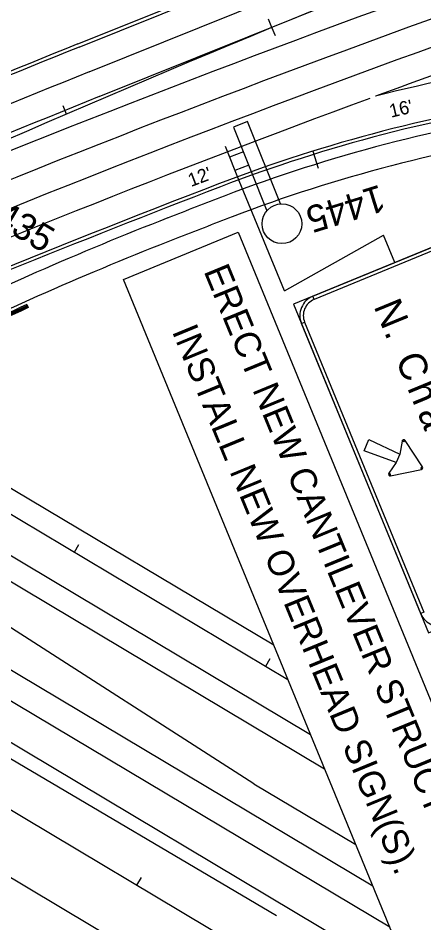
# Model space of a CAD drawing. Extents: x 2338610 to 2351914, y 366540 to 376484.
# Drawn here: x 2349654 to 2349836.1, y 367824.6 to 368230.7 of the extents above; entities that cross this region are included whole.
import ezdxf

# ---------------------------------------------------------------- set-up
doc = ezdxf.new("R2010")
doc.units = 0
for name, color, linetype in [('RD_HC_Cl', 7, 'Continuous'), ('RD_HC_CL_Rel', 7, 'Continuous'), ('RD_PD_Final_LnLine', 7, 'Continuous'), ('RD_PD_Final_TrvlWay', 7, 'Continuous'), ('RD_PD_FOC', 7, 'Continuous'), ('RD_PD_GR', 7, 'Continuous'), ('RD_PD_GrRail', 7, 'Continuous'), ('RD_PD_PaveShd', 7, 'Continuous'), ('RD_PD_SW', 7, 'Continuous'), ('RD_PD_WallFill', 7, 'Continuous'), ('TR SN EXTRUDED PANEL SIGNS- MOUNTED OVERHEAD', 7, 'Continuous'), ('TR SN UNASSIGNED 4', 7, 'Continuous'), ('TR SN UNASSIGNED 7', 7, 'Continuous')]:
    doc.layers.add(name, color=color, linetype=linetype)

msp = doc.modelspace()

# ---------------------------------------------------------------- linework, layer by layer
at = {"layer": 'RD_HC_Cl'}
msp.add_line((2346281.57, 369885.43), (2351112.4, 367003.22), dxfattribs=at)
msp.add_arc((2351947.82, 362927.74), 5729.58, 109.588035, 115.940729, dxfattribs=at)
at = {"layer": 'RD_HC_CL_Rel'}
msp.add_line((2349328.8, 368200.11), (2349775.06, 367933.86), dxfattribs=at)
msp.add_arc((2349988.36, 367521.67), 680, 98.07798, 111.03168, dxfattribs=at)
at = {"layer": 'RD_PD_Final_LnLine'}
for p, q in [((2348620.92, 368538.62), (2349820.78, 367822.75)), ((2349685.87, 368206.54), (2349804.82, 368254.4)), ((2349690.35, 368195.41), (2349809.3, 368243.27))]:
    msp.add_line(p, q, dxfattribs=at)
for centre, radius, start, end in [((2351783.35, 362853.29), 5729.58, 109.588035, 115.940729), ((2351783.35, 362853.29), 5717.58, 109.58804, 115.94073), ((2351783.35, 362853.29), 5705.58, 109.58804, 115.94073), ((2351828.87, 362879.88), 5741.58, 111.915714, 115.940729), ((2351783.35, 362853.29), 5693.58, 110.25944, 115.94073), ((2351828.87, 362879.88), 5729.58, 111.915714, 115.940729)]:
    msp.add_arc(centre, radius, start, end, dxfattribs=at)
at = {"layer": 'RD_PD_Final_TrvlWay'}
for p, q in [((2348626.93, 368549.01), (2349813.16, 367841.27)), ((2349681.39, 368217.67), (2349800.35, 368265.53)), ((2349328.8, 368200.11), (2349775.06, 367933.86)), ((2349320.61, 368186.37), (2349785.22, 367909.17))]:
    msp.add_line(p, q, dxfattribs=at)
for centre, radius, start, end in [((2351828.87, 362879.88), 5753.58, 111.915714, 113.768054), ((2351783.35, 362853.29), 5693.58, 109.58804, 110.23166), ((2349988.36, 367521.67), 696, 98.07798, 104.47302), ((2349988.36, 367521.67), 680, 98.07798, 111.03168), ((2351783.35, 362853.29), 5681.58, 111.03168, 115.94073)]:
    msp.add_arc(centre, radius, start, end, dxfattribs=at)
at = {"layer": 'RD_PD_FOC'}
msp.add_line((2349680.83, 368219.07), (2349799.79, 368266.92), dxfattribs=at)
for centre, radius, start, end in [((2351828.87, 362879.88), 5755.08, 111.915714, 113.768054), ((2349988.36, 367521.67), 678.5, 98.07798, 111.03168), ((2351783.35, 362853.29), 5680.08, 111.03168, 113.09877)]:
    msp.add_arc(centre, radius, start, end, dxfattribs=at)
at = {"layer": 'RD_PD_GR'}
for p, q in [((2349621.98, 368036.84), (2349768.71, 367949.3)), ((2349590.52, 368013.69), (2349791.57, 367893.74))]:
    msp.add_line(p, q, dxfattribs=at)
at = {"layer": 'RD_PD_GrRail'}
for p, q in [((2349558.12, 368016.57), (2349759.86, 367887.11)), ((2349769.99, 367827.67), (2349498.86, 367987.72)), ((2349759.83, 367887.06), (2349805.54, 367859.79))]:
    msp.add_line(p, q, dxfattribs=at)
at = {"layer": 'RD_PD_PaveShd'}
for p, q in [((2349612.02, 368042.78), (2349768.71, 367949.3)), ((2349573.34, 368023.94), (2349791.57, 367893.74)), ((2349506.94, 367991.36), (2350200.36, 367577.64)), ((2349475.16, 367949.69), (2350173.67, 367533.02))]:
    msp.add_line(p, q, dxfattribs=at)
at = {"layer": 'RD_PD_SW'}
for centre, radius, start, end in [((2349988.36, 367521.67), 674, 98.07798, 111.03168), ((2349988.36, 367521.67), 664, 98.07798, 111.03168), ((2351783.35, 362853.29), 5675.58, 111.03168, 111.30456), ((2351783.35, 362853.29), 5665.58, 111.03168, 111.30456), ((2350269.88, 366734.2), 1510, 111.30456, 116.14693), ((2350269.88, 366734.2), 1500, 111.30456, 116.14693)]:
    msp.add_arc(centre, radius, start, end, dxfattribs=at)
at = {"layer": 'RD_PD_WallFill'}
msp.add_line((2349657.97, 368102.07), (2349658.58, 368100.7), dxfattribs=at)
for radius in [1498.5, 1498, 1497.5, 1497]:
    msp.add_arc((2350269.88, 366734.2), radius, 114.10151, 116.14693, dxfattribs=at)
at = {"layer": 'TR SN EXTRUDED PANEL SIGNS- MOUNTED OVERHEAD'}
for p, q in [((2349753.21, 368157.55), (2349747.01, 368173.05)), ((2349755.09, 368170.65), (2349748.9, 368168.17)), ((2349757.48, 368164.68), (2349751.31, 368162.21)), ((2349773.49, 368108.26), (2349753.21, 368157.55)), ((2349773.49, 368108.26), (2349818.03, 368133.29)), ((2349823.1, 368120.96), (2349818.03, 368133.29)), ((2349786.83, 368104.35), (2349786.24, 368105.8)), ((2349781.13, 368093.55), (2349782.58, 368094.15)), ((2349826.28, 368040.73), (2349827.05, 368040.61)), ((2349827.05, 368040.61), (2349827.7, 368041.04)), ((2349835.48, 368029.22), (2349834.82, 368028.79)), ((2349834.82, 368028.79), (2349834.98, 368028.02)), ((2349820.96, 368026), (2349820.32, 368026.46)), ((2349821.11, 368025.23), (2349820.96, 368026)), ((2349836.11, 367964.03), (2349834.66, 367963.44))]:
    msp.add_line(p, q, dxfattribs=at)
msp.add_lwpolyline([(2349771.68, 368147.24), (2349756.89, 368184.21), (2349750.67, 368181.72), (2349765.67, 368144.2)], dxfattribs=at)
for points in [[(2349777.56, 368102.23), (2349838.23, 367954.76), (2349929.31, 367992.23), (2349868.65, 368139.7), (2349777.56, 368102.23), (2349777.56, 368102.23)], [(2349752.7, 368134.51), (2349879.78, 367825.61), (2349828.31, 367804.44), (2349701.23, 368113.34)], [(2349860.57, 368134.69), (2349786.83, 368104.35), (2349786.24, 368105.8), (2349859.97, 368136.13), (2349860.57, 368134.69), (2349860.57, 368134.69)], [(2349782.58, 368094.15), (2349836.11, 367964.03), (2349834.66, 367963.44), (2349781.13, 368093.55), (2349782.58, 368094.15), (2349782.58, 368094.15)], [(2349809.24, 368036.49), (2349811.35, 368041.54), (2349825.35, 368035.01), (2349823.73, 368031.14), (2349809.24, 368036.49), (2349809.24, 368036.49)], [(2349834.82, 368028.79), (2349835.48, 368029.22), (2349827.7, 368041.04), (2349827.05, 368040.61), (2349826.28, 368040.73), (2349825.35, 368035.01), (2349823.73, 368031.14), (2349820.32, 368026.46), (2349820.96, 368026), (2349821.11, 368025.23), (2349834.98, 368028.02), (2349834.82, 368028.79), (2349834.82, 368028.79)]]:
    msp.add_lwpolyline(points, close=True, dxfattribs=at)
msp.add_circle((2349772.4, 368138.36), 8.91, dxfattribs=at)
for centre, radius, start, end in [((2349789.81, 368097.12), 9.38, 112.3624, 202.3626), ((2349789.81, 368097.12), 7.82, 112.3624, 202.3626), ((2349827.05, 368040.61), 0.782, 33.3429, 170.8087), ((2349834.82, 368028.79), 0.782, 281.3821, 33.3432), ((2349820.96, 368026), 0.782, 143.9163, 281.3821), ((2349843.34, 367967), 9.38, 202.3626, 292.3628)]:
    msp.add_arc(centre, radius, start, end, dxfattribs=at)
at = {"layer": 'TR SN UNASSIGNED 7'}
for p, q in [((2349767.92, 368226.43), (2349766.4, 368230.13)), ((2349769.44, 368222.73), (2349767.92, 368226.43)), ((2349675.77, 368187.58), (2349674.19, 368191.25)), ((2349786.28, 368170.95), (2349788.65, 368163.31)), ((2349679.24, 367991.03), (2349681.29, 367994.47)), ((2349765.12, 367939.8), (2349767.17, 367943.23)), ((2349707.26, 367841.57), (2349709.31, 367845))]:
    msp.add_line(p, q, dxfattribs=at)

# ---------------------------------------------------------------- texts
at = {"layer": 'RD_PD_Final_TrvlWay'}
for s, rotation, p in [("16'", 13.289, (2349821.36, 368185.93)), ("12'", 20.6028, (2349731.6, 368154.82))]:
    msp.add_text(s, height=6, rotation=rotation, dxfattribs=at).set_placement(p)
at = {"layer": 'TR SN EXTRUDED PANEL SIGNS- MOUNTED OVERHEAD'}
for s, height, rotation, p in [('ERECT NEW CANTILEVER STRUCTURE.', 11.7187, 292.3626, (2349737.14, 368117.13)), ('N', 12.51, 292.3625, (2349813.43, 368101.34)), ('INSTALL NEW OVERHEAD SIGN(S).', 11.7187, 292.3626, (2349722.9, 368090.12)), ('.', 12.51, 292.3625, (2349818.17, 368089.81)), ('C', 12.51, 292.3625, (2349823.17, 368077.67)), ('h', 12.51, 292.3625, (2349828.52, 368064.66)), ('a', 12.51, 292.3625, (2349833.07, 368053.59))]:
    msp.add_text(s, height=height, rotation=rotation, dxfattribs=at).set_placement(p)
at = {"layer": 'TR SN UNASSIGNED 4'}
msp.add_text('I-526 WEST', height=25, rotation=329.4094, dxfattribs=at).set_placement((2349489.08, 367845.27))
at = {"layer": 'TR SN UNASSIGNED 7'}
for s, rotation, p in [('1445', 197.2882, (2349816.31, 368156.04)), ('1435', 329.1785, (2349634.86, 368143.28))]:
    msp.add_text(s, height=12, rotation=rotation, dxfattribs=at).set_placement(p)

doc.saveas('drawing.dxf')
